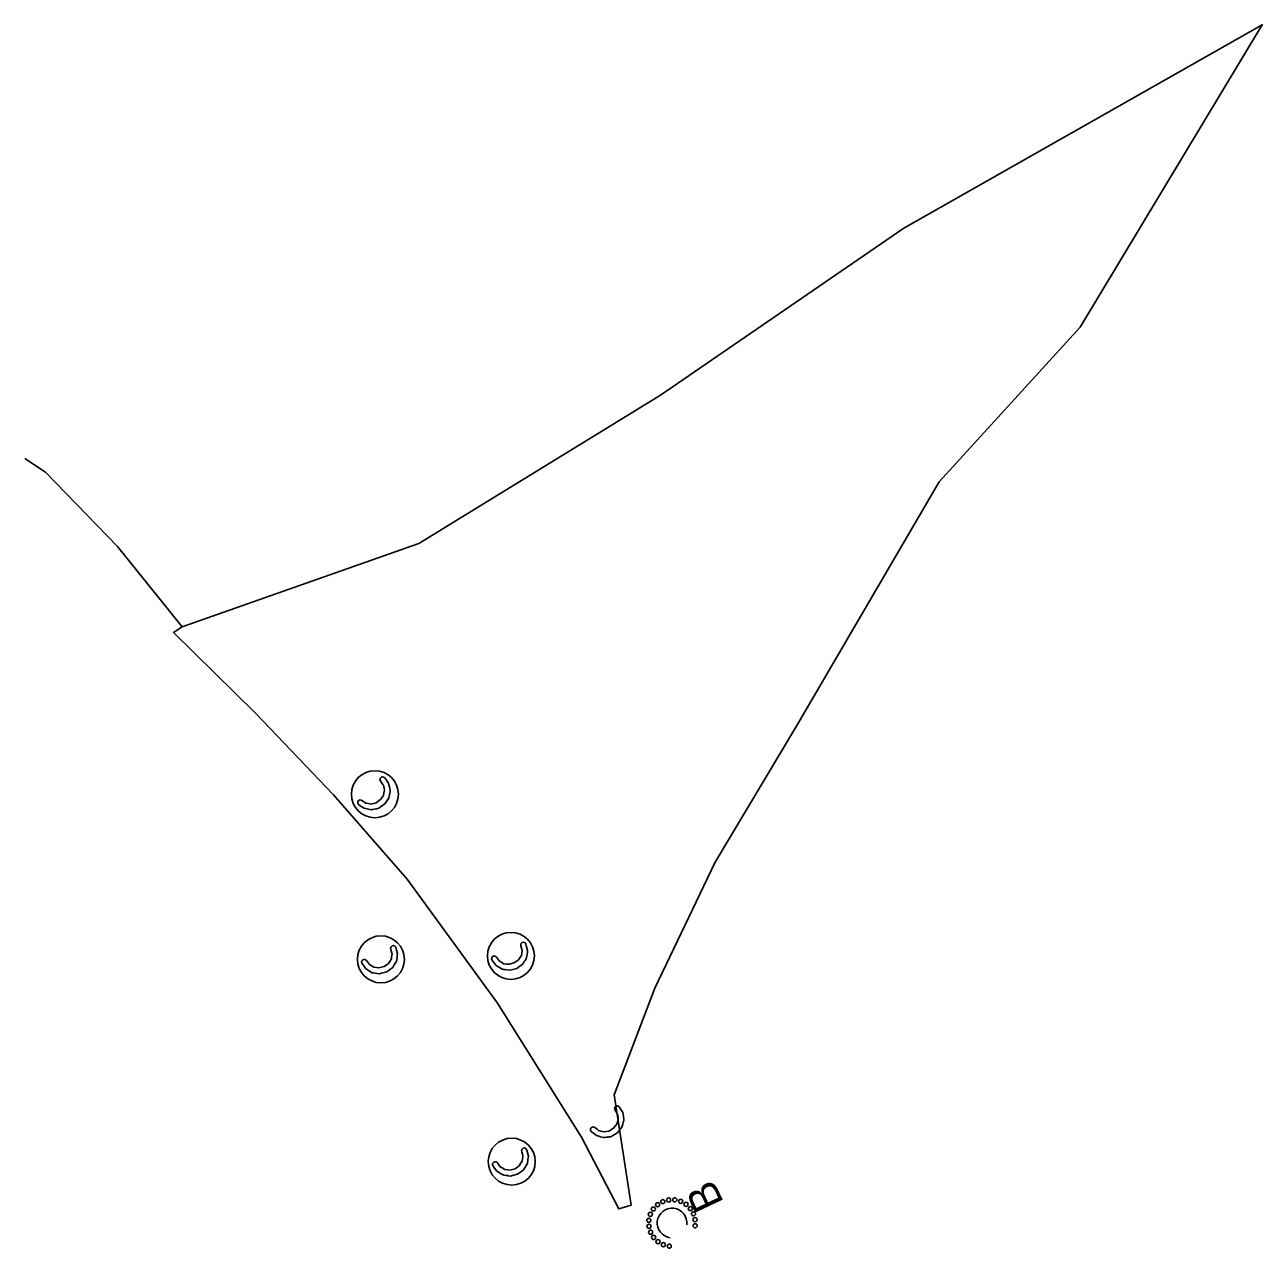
# Model space of a CAD drawing. Extents: x 400935 to 481562, y 415700 to 505362.
# Drawn here: x 477447 to 478053, y 499570 to 500169 of the extents above; entities that cross this region are included whole.
import ezdxf

# ---------------------------------------------------------------- set-up
doc = ezdxf.new("R2010")
doc.units = 0
for name, color, linetype in [('Coir Fiber Wattle Final CELL', 7, 'Continuous'), ('Coir Fiber Wattle with PAM Final CELL', 7, 'Continuous'), ('Label B Final CELL', 7, 'Continuous'), ('Rock Pipe Inlet Sediment Trap Type B Final CELL', 7, 'Continuous'), ('Scratch_Level_4', 7, 'Continuous'), ('Temporary Silt Fence Final', 7, 'Continuous')]:
    doc.layers.add(name, color=color, linetype=linetype)

msp = doc.modelspace()

# ---------------------------------------------------------------- linework, layer by layer
at = {"layer": 'Coir Fiber Wattle Final CELL'}
for p, q in [((477737.11, 499636.23), (477736.17, 499637.84)), ((477737.11, 499636.23), (477737.27, 499635.94)), ((477737.49, 499634.48), (477737.27, 499635.94)), ((477726.18, 499629.36), (477727.39, 499628.38)), ((477732.97, 499627.61), (477735.23, 499628.96)), ((477735.24, 499628.97), (477735.23, 499628.96)), ((477735.24, 499628.97), (477736.85, 499630.93)), ((477736.85, 499630.93), (477737.21, 499632.08)), ((477737.21, 499632.08), (477737.63, 499633.46)), ((477737.63, 499633.46), (477737.49, 499634.48)), ((477727.39, 499628.38), (477728.01, 499627.89)), ((477728.01, 499627.89), (477729.07, 499627.59)), ((477729.07, 499627.59), (477730.47, 499627.21)), ((477730.7, 499627.24), (477730.47, 499627.21)), ((477730.7, 499627.24), (477731.8, 499627.42)), ((477732.97, 499627.61), (477731.8, 499627.42))]:
    msp.add_line(p, q, dxfattribs=at)
msp.add_lwpolyline([(477738.13, 499639.54), (477738.94, 499638.21), (477739.87, 499636.65), (477740, 499635.83), (477740.14, 499634.83), (477740.41, 499633.05), (477740.4, 499633.01), (477740.28, 499632.59), (477740.26, 499632.51), (477739.99, 499631.59), (477739.81, 499630.95), (477739.41, 499629.54), (477738.77, 499628.73), (477737.19, 499626.72), (477737.18, 499626.72), (477734.9, 499625.39), (477734.01, 499624.87), (477732.89, 499624.73), (477732.65, 499624.69), (477731.7, 499624.57), (477730.98, 499624.47), (477730.8, 499624.45), (477730.44, 499624.41), (477730.43, 499624.41), (477728.98, 499624.83), (477727.69, 499625.2), (477726.92, 499625.43), (477725.53, 499626.51), (477724.31, 499627.46)], dxfattribs=at)
for centre, radius, start in [((477737.15, 499638.69), 1.3, 40.99275), ((477725.32, 499628.34), 1.33, 49.88011)]:
    msp.add_arc(centre, radius, start, 220.99275, dxfattribs=at)
at = {"layer": 'Coir Fiber Wattle with PAM Final CELL'}
for p, q in [((477622.38, 499797.34), (477621.31, 499798.87)), ((477622.38, 499797.34), (477622.57, 499797.07)), ((477622.91, 499795.63), (477622.57, 499797.07)), ((477622.58, 499792.04), (477622.83, 499793.22)), ((477622.83, 499793.22), (477623.14, 499794.63)), ((477623.14, 499794.63), (477622.91, 499795.63)), ((477612.08, 499789.55), (477613.37, 499788.69)), ((477613.37, 499788.69), (477614.03, 499788.25)), ((477614.03, 499788.25), (477615.11, 499788.05)), ((477615.11, 499788.05), (477616.54, 499787.78)), ((477616.77, 499787.84), (477616.54, 499787.78)), ((477616.77, 499787.84), (477617.85, 499788.1)), ((477619, 499788.39), (477617.85, 499788.1)), ((477619, 499788.39), (477621.13, 499789.94)), ((477621.14, 499789.94), (477621.13, 499789.94)), ((477621.14, 499789.94), (477622.58, 499792.04)), ((477626.72, 499714.77), (477626.25, 499716.58)), ((477626.61, 499712.98), (477626.8, 499714.45)), ((477626.72, 499714.77), (477626.8, 499714.45)), ((477689.39, 499712.45), (477690.17, 499713.66)), ((477690.42, 499716.47), (477689.95, 499718.27)), ((477690.17, 499713.66), (477690.31, 499714.68)), ((477690.31, 499714.68), (477690.5, 499716.15)), ((477690.42, 499716.47), (477690.5, 499716.15)), ((477614.34, 499711.11), (477615.24, 499709.85)), ((477615.24, 499709.85), (477615.7, 499709.21)), ((477615.7, 499709.21), (477616.64, 499708.63)), ((477616.64, 499708.63), (477617.88, 499707.88)), ((477618.12, 499707.85), (477617.88, 499707.88)), ((477618.12, 499707.85), (477619.22, 499707.72)), ((477620.4, 499707.59), (477619.22, 499707.72)), ((477620.4, 499707.59), (477622.94, 499708.28)), ((477622.95, 499708.28), (477622.94, 499708.28)), ((477622.95, 499708.28), (477625.04, 499709.74)), ((477625.04, 499709.74), (477625.69, 499710.75)), ((477625.69, 499710.75), (477626.47, 499711.97)), ((477626.47, 499711.97), (477626.61, 499712.98)), ((477678.04, 499712.81), (477678.94, 499711.55)), ((477678.94, 499711.55), (477679.4, 499710.9)), ((477679.4, 499710.9), (477680.34, 499710.33)), ((477680.34, 499710.33), (477681.58, 499709.58)), ((477681.81, 499709.55), (477681.58, 499709.58)), ((477681.81, 499709.55), (477682.92, 499709.42)), ((477684.1, 499709.29), (477682.92, 499709.42)), ((477684.1, 499709.29), (477686.64, 499709.98)), ((477686.65, 499709.98), (477686.64, 499709.98)), ((477686.65, 499709.98), (477688.73, 499711.44)), ((477688.73, 499711.44), (477689.39, 499712.45)), ((477690.83, 499615.68), (477690.36, 499617.48)), ((477678.45, 499612.02), (477679.35, 499610.76)), ((477679.35, 499610.76), (477679.81, 499610.12)), ((477687.06, 499609.19), (477689.15, 499610.65)), ((477689.15, 499610.65), (477689.8, 499611.66)), ((477689.8, 499611.66), (477690.58, 499612.88)), ((477690.58, 499612.88), (477690.72, 499613.89)), ((477690.72, 499613.89), (477690.91, 499615.36)), ((477690.83, 499615.68), (477690.91, 499615.36)), ((477679.81, 499610.12), (477680.75, 499609.54)), ((477680.75, 499609.54), (477681.99, 499608.79)), ((477682.23, 499608.76), (477681.99, 499608.79)), ((477682.23, 499608.76), (477683.33, 499608.63)), ((477684.51, 499608.5), (477683.33, 499608.63)), ((477684.51, 499608.5), (477687.05, 499609.19)), ((477687.06, 499609.19), (477687.05, 499609.19))]:
    msp.add_line(p, q, dxfattribs=at)
for points in [[(477623.11, 499800.73), (477624.03, 499799.47), (477625.1, 499798), (477625.29, 499797.19), (477625.52, 499796.2), (477625.94, 499794.46), (477625.93, 499794.42), (477625.85, 499793.99), (477625.83, 499793.91), (477625.65, 499792.97), (477625.53, 499792.32), (477625.25, 499790.88), (477624.68, 499790.01), (477623.28, 499787.88), (477623.27, 499787.87), (477621.11, 499786.35), (477620.27, 499785.76), (477619.17, 499785.52), (477618.93, 499785.46), (477617.99, 499785.26), (477617.28, 499785.1), (477617.11, 499785.07), (477616.76, 499784.99), (477616.75, 499784.99), (477615.27, 499785.28), (477613.95, 499785.54), (477613.16, 499785.7), (477611.68, 499786.66), (477610.39, 499787.51)], [(477628.6, 499717.68), (477629.01, 499716.18), (477629.5, 499714.43), (477629.39, 499713.6), (477629.26, 499712.6), (477629.03, 499710.82), (477629.01, 499710.78), (477628.78, 499710.41), (477628.74, 499710.34), (477628.24, 499709.53), (477627.89, 499708.96), (477627.13, 499707.71), (477626.29, 499707.1), (477624.22, 499705.6), (477624.21, 499705.59), (477621.66, 499704.93), (477620.66, 499704.68), (477619.54, 499704.84), (477619.31, 499704.87), (477618.36, 499705.01), (477617.63, 499705.11), (477617.46, 499705.14), (477617.1, 499705.19), (477617.09, 499705.19), (477615.81, 499705.99), (477614.67, 499706.7), (477613.98, 499707.13), (477612.94, 499708.55), (477612.03, 499709.8)], [(477692.3, 499719.38), (477692.71, 499717.88), (477693.19, 499716.13), (477693.09, 499715.3), (477692.96, 499714.3), (477692.73, 499712.52), (477692.71, 499712.48), (477692.48, 499712.11), (477692.44, 499712.04), (477691.94, 499711.23), (477691.59, 499710.66), (477690.82, 499709.41), (477689.98, 499708.8), (477687.92, 499707.3), (477687.91, 499707.29), (477685.36, 499706.63), (477684.36, 499706.37), (477683.24, 499706.54), (477683, 499706.57), (477682.05, 499706.71), (477681.33, 499706.81), (477681.16, 499706.84), (477680.8, 499706.89), (477680.79, 499706.89), (477679.51, 499707.69), (477678.37, 499708.4), (477677.68, 499708.83), (477676.64, 499710.25), (477675.72, 499711.49)], [(477692.71, 499618.59), (477693.12, 499617.09), (477693.6, 499615.34), (477693.5, 499614.51), (477693.37, 499613.51), (477693.14, 499611.73), (477693.12, 499611.69), (477692.89, 499611.32), (477692.85, 499611.25), (477692.35, 499610.44), (477692, 499609.87), (477691.24, 499608.62), (477690.4, 499608.01), (477688.33, 499606.51), (477688.32, 499606.5), (477685.77, 499605.84), (477684.77, 499605.59), (477683.65, 499605.75), (477683.42, 499605.78), (477682.47, 499605.92), (477681.74, 499606.02), (477681.57, 499606.05), (477681.21, 499606.1), (477681.2, 499606.1), (477679.92, 499606.9), (477678.78, 499607.61), (477678.09, 499608.04), (477677.05, 499609.46), (477676.14, 499610.71)]]:
    msp.add_lwpolyline(points, dxfattribs=at)
for centre in [(477618.42, 499792.6), (477621.34, 499711.73), (477685.04, 499713.43), (477685.45, 499612.64)]:
    msp.add_circle(centre, 11.5, dxfattribs=at)
for centre, radius, start, end in [((477622.21, 499799.8), 1.3, 45.94189, 225.94189), ((477611.31, 499788.46), 1.33, 54.82925, 225.94189), ((477691.12, 499718.83), 1.3, 25.2938, 205.2938), ((477627.43, 499717.13), 1.3, 25.2938, 205.2938), ((477613.23, 499710.37), 1.33, 34.18117, 205.2938), ((477676.93, 499712.06), 1.33, 34.18117, 205.2938), ((477691.54, 499618.04), 1.3, 25.2938, 205.2938), ((477677.34, 499611.28), 1.33, 34.18117, 205.2938)]:
    msp.add_arc(centre, radius, start, end, dxfattribs=at)
at = {"layer": 'Rock Pipe Inlet Sediment Trap Type B Final CELL'}
for centre in [(477756.88, 499591.55), (477759.44, 499593.07), (477762.31, 499593.88), (477765.3, 499593.92), (477768.19, 499593.18), (477770.79, 499591.72), (477753.34, 499586.81), (477754.8, 499589.41), (477772.92, 499589.64), (477774.45, 499587.08), (477752.6, 499583.92), (477752.64, 499580.94), (477775.25, 499584.21), (477775.29, 499581.23), (477753.45, 499578.07), (477754.97, 499575.51), (477757.11, 499573.42), (477759.71, 499571.97), (477762.6, 499571.23)]:
    msp.add_circle(centre, 1.01, dxfattribs=at)
msp.add_arc((477763.95, 499582.57), 7.26, 353.22395, 263.21514, dxfattribs=at)
at = {"layer": 'Scratch_Level_4'}
msp.add_lwpolyline([(477743.89, 499591.25), (477735.57, 499645.34), (477755.61, 499697.57), (477785.09, 499759.26), (477825.1, 499826.28), (477894.84, 499945.54), (477963.94, 500021.38), (478053.04, 500169.49), (477877.48, 500069.82), (477758.35, 499988.01), (477640.01, 499915.43), (477524.02, 499874.59), (477519.73, 499871.76), (477560.06, 499832.22), (477598.12, 499792.35), (477634.17, 499751.04), (477678.41, 499690.34), (477719.6, 499624.56), (477737.96, 499589.47)], close=True, dxfattribs=at)
at = {"layer": 'Temporary Silt Fence Final'}
msp.add_lwpolyline([(477524.02, 499874.59), (477524.02, 499874.59), (477492.33, 499913.92), (477457.05, 499950.42), (477446.91, 499957.08)], dxfattribs=at)

# ---------------------------------------------------------------- texts
at = {"layer": 'Label B Final CELL'}
msp.add_text('B', height=15, rotation=115.2938, dxfattribs=at).set_placement((477789.49, 499592.53))

doc.saveas('drawing.dxf')
